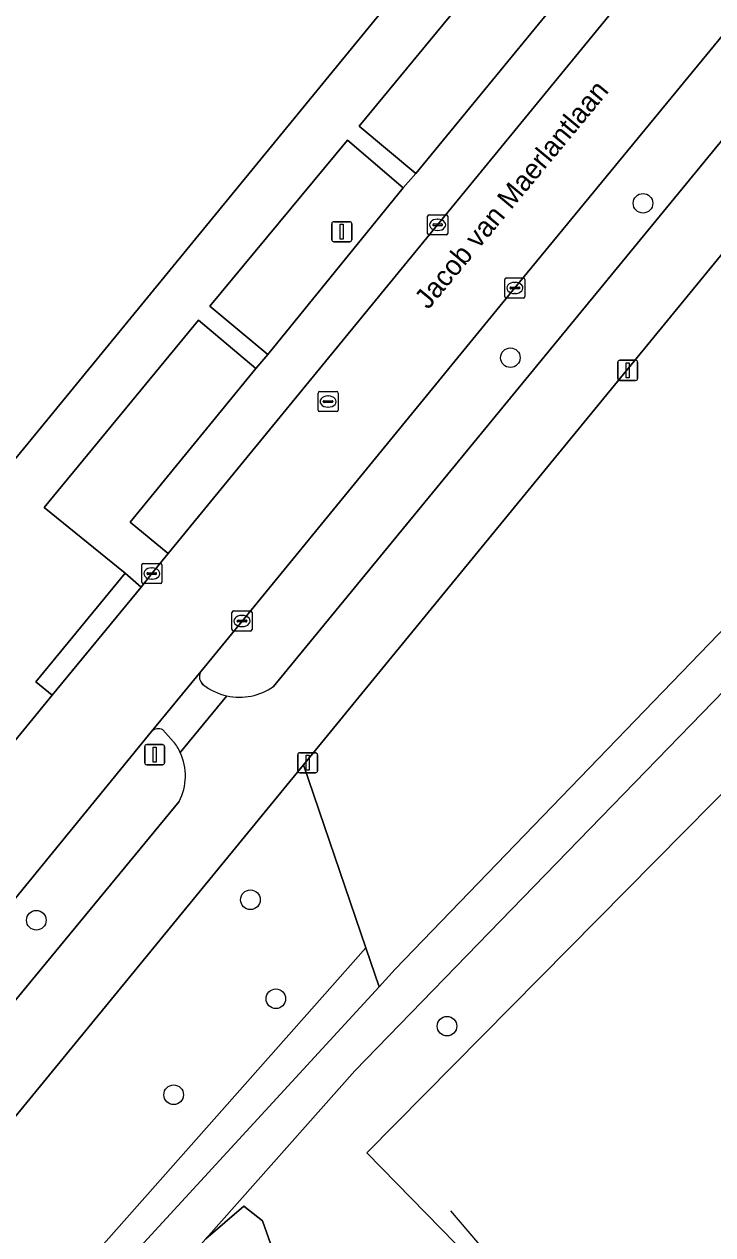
# Model space of a CAD drawing. Extents: x 160349 to 161355, y 381727 to 382854.
# Drawn here: x 160934.1 to 160968.5, y 381971.4 to 382031.7 of the extents above; entities that cross this region are included whole.
import ezdxf

# ---------------------------------------------------------------- set-up
doc = ezdxf.new("R2010")
doc.units = 0
for name, color, linetype in [('IMGEO_Berm_groen', 7, 'Continuous'), ('IMGEO_Boom', 7, 'Continuous'), ('IMGEO_Fietspad_gesloten', 7, 'Continuous'), ('IMGEO_Fietspad_open', 7, 'Continuous'), ('IMGEO_Groenvoorziening', 7, 'Continuous'), ('IMGEO_Hek', 7, 'Continuous'), ('IMGEO_Kolk', 7, 'Continuous'), ('IMGEO_Lichtmast', 7, 'Continuous'), ('IMGEO_Openbare_ruimte_label', 7, 'Continuous'), ('IMGEO_Parkeervlak_open', 7, 'Continuous'), ('IMGEO_Rijbaan_lokaal_open', 7, 'Continuous'), ('IMGEO_Rioolput', 7, 'Continuous'), ('IMGEO_Voetpad_gesloten', 7, 'Continuous'), ('IMGEO_Voetpad_open', 7, 'Continuous')]:
    doc.layers.add(name, color=color, linetype=linetype)

msp = doc.modelspace()

# ---------------------------------------------------------------- linework, layer by layer
at = {"layer": 'IMGEO_Berm_groen'}
for points in [[(160977.843, 382041.946), (160973.022, 382036.094), (160970.983, 382033.618), (160958.625, 382018.578), (160945.001, 382001.967), (160942.965, 381999.472)], [(160946.577, 381998.701), (160947.644, 382000), (160978.867, 382038.025)], [(160942.999, 381998.87), (160943.066, 381998.791)], [(160940.487, 381996.462), (160931.458, 381985.432), (160917.822, 381968.839), (160910.403, 381959.801)], [(160941.587, 381995.948), (160941.049, 381996.534)], [(160914.252, 381959.514), (160941.867, 381992.967)]]:
    msp.add_lwpolyline(points, dxfattribs=at)
for centre, radius, start, end in [((160943.351, 381999.192), 0.477, 144.00703, 222.45805), ((160944.889, 382001.119), 2.957, 231.94134, 257.44147), ((160944.88, 382001.112), 2.948, 257.57231, 305.13262), ((160940.815, 381996.128), 0.468, 60.06083, 134.5404), ((160939.335, 381994.194), 2.854, 25.27298, 37.90616), ((160939.409, 381994.24), 2.768, 332.62628, 25.07844)]:
    msp.add_arc(centre, radius, start, end, dxfattribs=at)
at = {"layer": 'IMGEO_Boom'}
for centre in [(160965.021, 382022.803), (160958.4, 382015.1), (160945.421, 381988.065), (160934.732, 381987.042), (160946.691, 381983.127), (160955.234, 381981.759), (160941.589, 381978.338)]:
    msp.add_circle(centre, 0.489, dxfattribs=at)
at = {"layer": 'IMGEO_Fietspad_gesloten'}
for points in [[(160920.972, 381961.771), (160930.015, 381972.797), (160948.063, 381994.801), (160952.327, 382000), (160980.31, 382034.118), (160983.19, 382037.204), (160985.736, 382040.033), (160986.476, 382040.855), (160994.96, 382049.954), (161000, 382055.359), (161018.426, 382075.121), (161020.27, 382077.268), (161020.313, 382077.319), (161024.035, 382081.674), (161027.907, 382086.255)], [(161008.328, 382069.561), (161008.144, 382069.364), (161000, 382060.672), (160992.234, 382052.382), (160984.775, 382044.42), (160984.715, 382044.355), (160984.593, 382044.223), (160978.867, 382038.025), (160947.644, 382000), (160946.577, 381998.701)], [(160944.246, 381998.233), (160941.916, 381995.413)], [(160941.867, 381992.967), (160914.252, 381959.514)]]:
    msp.add_lwpolyline(points, dxfattribs=at)
for centre, radius, start, end in [((160944.88, 382001.112), 2.948, 257.57231, 305.13262), ((160939.409, 381994.24), 2.768, 332.62628, 25.07844)]:
    msp.add_arc(centre, radius, start, end, dxfattribs=at)
at = {"layer": 'IMGEO_Fietspad_open'}
for points in [[(160942.965, 381999.472), (160940.487, 381996.462)], [(160943.066, 381998.791), (160942.999, 381998.87)], [(160941.916, 381995.413), (160944.246, 381998.233)], [(160941.049, 381996.534), (160941.587, 381995.948)]]:
    msp.add_lwpolyline(points, dxfattribs=at)
for centre, radius, start, end in [((160943.351, 381999.192), 0.477, 144.00703, 222.45805), ((160944.889, 382001.119), 2.957, 231.94134, 257.44147), ((160940.815, 381996.128), 0.468, 60.06083, 134.5404), ((160939.335, 381994.194), 2.854, 25.27298, 37.90616)]:
    msp.add_arc(centre, radius, start, end, dxfattribs=at)
at = {"layer": 'IMGEO_Groenvoorziening'}
for points in [[(160924.933, 382013.986), (160932.226, 382008.305), (160932.496, 382008.634), (160958.918, 382040.842)], [(160983.19, 382037.204), (160980.31, 382034.118), (160952.327, 382000), (160948.063, 381994.801), (160951.191, 381985.661), (160951.842, 381983.726), (160952.645, 381984.6), (160971.09, 382003.681), (160987.697, 382019.509)], [(160995.662, 382024.232), (160976.91, 382006.573), (160950.642, 381979.531), (160943.189, 381971.147), (160945.096, 381972.781), (160946.03, 381972.056), (160948.417, 381965.264), (160952.303, 381955.561), (160957.216, 381943.291), (160957.707, 381940.783), (160965.908, 381946.927), (160989.311, 381962.789)], [(160951.842, 381983.726), (160951.191, 381985.661), (160932.182, 381964.238), (160927.224, 381957.496), (160920.972, 381961.771), (160890.52, 381924.643)], [(160890.677, 381907.844), (160891.108, 381907.876), (160894.311, 381908.969), (160895.463, 381909.644), (160898.554, 381913.782), (160906.494, 381926.014), (160914.767, 381938.069), (160926.176, 381953.998), (160935.546, 381965.997), (160951.842, 381983.726)], [(160948.417, 381965.264), (160946.03, 381972.056), (160945.096, 381972.781), (160943.189, 381971.147)]]:
    msp.add_lwpolyline(points, dxfattribs=at)
for points in [[(160960.19, 382032.206), (160957.382, 382034.583), (160950.845, 382026.65), (160953.681, 382024.287)], [(160953.052, 382023.567), (160950.264, 382025.949), (160943.394, 382017.663), (160946.289, 382015.257)], [(160945.685, 382014.567), (160942.823, 382016.971), (160935.129, 382007.623), (160939.169, 382004.356), (160939.968, 382003.663), (160940.499, 382004.335), (160941.313, 382005.329), (160939.424, 382006.895)], [(160988.316, 381984.387), (160974.279, 381998.738), (160951.234, 381975.44), (160965.27, 381961.089)], [(160965.27, 381961.089), (160951.234, 381975.44), (160974.279, 381998.738), (160988.316, 381984.387)], [(160951.191, 381985.661), (160948.063, 381994.801), (160930.015, 381972.797), (160920.972, 381961.771), (160927.224, 381957.496), (160932.182, 381964.238)]]:
    msp.add_lwpolyline(points, close=True, dxfattribs=at)
at = {"layer": 'IMGEO_Hek'}
for points in [[(160943.189, 381971.147), (160945.096, 381972.781), (160946.03, 381972.056)], [(160955.411, 381972.552), (160961.967, 381964.86)], [(160946.03, 381972.056), (160948.417, 381965.264), (160952.303, 381955.561)]]:
    msp.add_lwpolyline(points, dxfattribs=at)
at = {"layer": 'IMGEO_Kolk'}
for p, q in [((160954.268, 382021.302), (160954.268, 382022.154)), ((160954.343, 382022.228), (160955.195, 382022.228)), ((160954.57, 382021.771), (160954.968, 382021.771)), ((160954.756, 382022.008), (160954.781, 382022.008)), ((160955.269, 382022.154), (160955.269, 382021.302)), ((160955.195, 382021.228), (160954.343, 382021.228)), ((160954.527, 382021.722), (160954.527, 382021.734)), ((160954.965, 382021.685), (160954.567, 382021.685)), ((160954.779, 382021.448), (160954.754, 382021.448)), ((160955.011, 382021.734), (160955.011, 382021.722)), ((160958.124, 382018.152), (160958.124, 382019.004)), ((160958.199, 382019.078), (160959.051, 382019.078)), ((160958.612, 382018.858), (160958.637, 382018.858)), ((160959.125, 382019.004), (160959.125, 382018.152)), ((160958.383, 382018.572), (160958.383, 382018.584)), ((160958.821, 382018.535), (160958.423, 382018.535)), ((160958.426, 382018.621), (160958.824, 382018.621)), ((160958.635, 382018.298), (160958.61, 382018.298)), ((160958.867, 382018.584), (160958.867, 382018.572)), ((160959.051, 382018.078), (160958.199, 382018.078)), ((160940.073, 382004.835), (160940.925, 382004.835)), ((160939.998, 382003.909), (160939.998, 382004.761)), ((160940.257, 382004.329), (160940.257, 382004.341)), ((160940.695, 382004.292), (160940.297, 382004.292)), ((160940.3, 382004.378), (160940.698, 382004.378)), ((160940.486, 382004.615), (160940.511, 382004.615)), ((160940.741, 382004.341), (160940.741, 382004.329)), ((160940.999, 382004.761), (160940.999, 382003.909)), ((160940.925, 382003.835), (160940.073, 382003.835)), ((160940.509, 382004.055), (160940.484, 382004.055)), ((160944.575, 382002.467), (160945.427, 382002.467)), ((160944.5, 382001.541), (160944.5, 382002.393)), ((160944.759, 382001.961), (160944.759, 382001.973)), ((160945.197, 382001.924), (160944.799, 382001.924)), ((160944.802, 382002.01), (160945.2, 382002.01)), ((160944.988, 382002.247), (160945.013, 382002.247)), ((160945.243, 382001.973), (160945.243, 382001.961)), ((160945.501, 382002.393), (160945.501, 382001.541)), ((160945.427, 382001.467), (160944.575, 382001.467)), ((160945.011, 382001.687), (160944.986, 382001.687))]:
    msp.add_line(p, q, dxfattribs=at)
for points in [[(160954.268, 382021.302), (160954.268, 382022.154)], [(160954.343, 382022.228), (160955.195, 382022.228)], [(160955.269, 382022.154), (160955.269, 382021.302)], [(160955.195, 382021.228), (160954.343, 382021.228)], [(160958.124, 382018.152), (160958.124, 382019.004)], [(160958.199, 382019.078), (160959.051, 382019.078)], [(160959.125, 382019.004), (160959.125, 382018.152)], [(160959.051, 382018.078), (160958.199, 382018.078)], [(160940.073, 382004.835), (160940.925, 382004.835)], [(160939.998, 382003.909), (160939.998, 382004.761)], [(160940.999, 382004.761), (160940.999, 382003.909)], [(160940.925, 382003.835), (160940.073, 382003.835)], [(160944.575, 382002.467), (160945.427, 382002.467)], [(160944.5, 382001.541), (160944.5, 382002.393)], [(160945.501, 382002.393), (160945.501, 382001.541)], [(160945.427, 382001.467), (160944.575, 382001.467)]]:
    msp.add_lwpolyline(points, dxfattribs=at)
for centre, radius, start, end in [((160954.345, 382022.152), 0.0765, 91.55205, 178.44795), ((160954.345, 382022.152), 0.0765, 91.55205, 178.44795), ((160954.567, 382021.731), 0.0403, 85.87752, 175.75265), ((160954.972, 382021.733), 0.0386, 1.73085, 96.63898), ((160955.193, 382022.152), 0.0765, 1.55205, 88.44795), ((160955.193, 382022.152), 0.0765, 1.55205, 88.44795), ((160954.345, 382021.304), 0.0765, 181.55205, 268.44795), ((160954.345, 382021.304), 0.0765, 181.55205, 268.44795), ((160954.564, 382021.721), 0.0366, 178.93798, 274.71019), ((160954.968, 382021.728), 0.043, 264.86636, 352.45326), ((160955.193, 382021.304), 0.0765, 271.55205, 358.44795), ((160955.193, 382021.304), 0.0765, 271.55205, 358.44795), ((160958.201, 382019.002), 0.0765, 91.55205, 178.44795), ((160958.201, 382019.002), 0.0765, 91.55205, 178.44795), ((160959.049, 382019.002), 0.0765, 1.55205, 88.44795), ((160959.049, 382019.002), 0.0765, 1.55205, 88.44795), ((160958.201, 382018.154), 0.0765, 181.55205, 268.44795), ((160958.201, 382018.154), 0.0765, 181.55205, 268.44795), ((160958.423, 382018.581), 0.0403, 85.87752, 175.75265), ((160958.42, 382018.571), 0.0366, 178.93798, 274.71019), ((160958.824, 382018.578), 0.043, 264.86636, 352.45326), ((160958.828, 382018.583), 0.0386, 1.73085, 96.63898), ((160959.049, 382018.154), 0.0765, 271.55205, 358.44795), ((160959.049, 382018.154), 0.0765, 271.55205, 358.44795), ((160940.075, 382004.759), 0.0765, 91.55205, 178.44795), ((160940.075, 382004.759), 0.0765, 91.55205, 178.44795), ((160940.923, 382004.759), 0.0765, 1.55205, 88.44795), ((160940.923, 382004.759), 0.0765, 1.55205, 88.44795), ((160940.297, 382004.338), 0.0403, 85.87752, 175.75265), ((160940.294, 382004.328), 0.0366, 178.93798, 274.71019), ((160940.698, 382004.335), 0.043, 264.86636, 352.45326), ((160940.702, 382004.34), 0.0386, 1.73085, 96.63898), ((160940.075, 382003.911), 0.0765, 181.55205, 268.44795), ((160940.075, 382003.911), 0.0765, 181.55205, 268.44795), ((160940.923, 382003.911), 0.0765, 271.55205, 358.44795), ((160940.923, 382003.911), 0.0765, 271.55205, 358.44795), ((160944.577, 382002.391), 0.0765, 91.55205, 178.44795), ((160944.577, 382002.391), 0.0765, 91.55205, 178.44795), ((160945.425, 382002.391), 0.0765, 1.55205, 88.44795), ((160945.425, 382002.391), 0.0765, 1.55205, 88.44795), ((160944.799, 382001.97), 0.0403, 85.87752, 175.75265), ((160944.796, 382001.96), 0.0366, 178.93798, 274.71019), ((160945.2, 382001.967), 0.043, 264.86636, 352.45326), ((160945.204, 382001.972), 0.0386, 1.73085, 96.63898), ((160944.577, 382001.543), 0.0765, 181.55205, 268.44795), ((160944.577, 382001.543), 0.0765, 181.55205, 268.44795), ((160945.425, 382001.543), 0.0765, 271.55205, 358.44795), ((160945.425, 382001.543), 0.0765, 271.55205, 358.44795)]:
    msp.add_arc(centre, radius, start, end, dxfattribs=at)
for centre, major_axis, ratio, start_param, end_param in [((160954.755, 382021.728), (-0.387, 0.002), 0.722429, 4.712389, 7.853982), ((160954.78, 382021.728), (-0.39, 0.002), 0.717154, 1.570796, 4.712389), ((160958.611, 382018.578), (-0.387, 0.002), 0.722429, 4.712389, 7.853982), ((160958.636, 382018.578), (-0.39, 0.002), 0.717154, 1.570796, 4.712389), ((160940.485, 382004.335), (-0.387, 0.002), 0.722429, 4.712389, 7.853982), ((160940.51, 382004.335), (-0.39, 0.002), 0.717154, 1.570796, 4.712389), ((160944.987, 382001.967), (-0.387, 0.002), 0.722429, 4.712389, 7.853982), ((160945.012, 382001.967), (-0.39, 0.002), 0.717154, 1.570796, 4.712389)]:
    msp.add_ellipse(centre, major_axis=major_axis, ratio=ratio, start_param=start_param, end_param=end_param, dxfattribs=at)
at = {"layer": 'IMGEO_Lichtmast'}
for p, q in [((160949.486, 382020.985), (160949.486, 382021.785)), ((160949.486, 382021.785), (160949.486, 382020.985)), ((160949.586, 382021.885), (160950.376, 382021.885)), ((160950.376, 382021.885), (160949.586, 382021.885)), ((160950.476, 382021.785), (160950.476, 382020.985)), ((160950.476, 382020.985), (160950.476, 382021.785)), ((160950.376, 382020.885), (160949.586, 382020.885)), ((160949.586, 382020.885), (160950.376, 382020.885)), ((160963.762, 382014.07), (160963.762, 382014.87)), ((160963.762, 382014.87), (160963.762, 382014.07)), ((160963.862, 382014.97), (160964.652, 382014.97)), ((160964.652, 382014.97), (160963.862, 382014.97)), ((160964.752, 382014.87), (160964.752, 382014.07)), ((160964.752, 382014.07), (160964.752, 382014.87)), ((160964.652, 382013.97), (160963.862, 382013.97)), ((160963.862, 382013.97), (160964.652, 382013.97)), ((160940.243, 381995.8), (160941.033, 381995.8)), ((160941.033, 381995.8), (160940.243, 381995.8)), ((160940.143, 381994.9), (160940.143, 381995.7)), ((160940.143, 381995.7), (160940.143, 381994.9)), ((160941.133, 381995.7), (160941.133, 381994.9)), ((160941.133, 381994.9), (160941.133, 381995.7)), ((160947.781, 381994.496), (160947.781, 381995.296)), ((160947.781, 381995.296), (160947.781, 381994.496)), ((160947.881, 381995.396), (160948.671, 381995.396)), ((160948.671, 381995.396), (160947.881, 381995.396)), ((160948.771, 381995.296), (160948.771, 381994.496)), ((160948.771, 381994.496), (160948.771, 381995.296)), ((160941.033, 381994.8), (160940.243, 381994.8)), ((160940.243, 381994.8), (160941.033, 381994.8)), ((160948.671, 381994.396), (160947.881, 381994.396)), ((160947.881, 381994.396), (160948.671, 381994.396))]:
    msp.add_line(p, q, dxfattribs=at)
for points in [[(160949.906, 382021.76), (160950.056, 382021.76), (160950.056, 382021.01), (160949.906, 382021.01), (160949.906, 382021.76)], [(160964.182, 382014.845), (160964.332, 382014.845), (160964.332, 382014.095), (160964.182, 382014.095), (160964.182, 382014.845)], [(160940.563, 381995.675), (160940.713, 381995.675), (160940.713, 381994.925), (160940.563, 381994.925), (160940.563, 381995.675)], [(160948.201, 381995.271), (160948.351, 381995.271), (160948.351, 381994.521), (160948.201, 381994.521), (160948.201, 381995.271)]]:
    msp.add_lwpolyline(points, dxfattribs=at)
for centre, start, end in [((160949.586, 382021.785), 90, 180), ((160949.586, 382021.785), 90, 180), ((160950.376, 382021.785), 0, 90), ((160950.376, 382021.785), 360, 90), ((160949.586, 382020.985), 180, 270), ((160949.586, 382020.985), 180, 270), ((160950.376, 382020.985), 270, 0), ((160950.376, 382020.985), 270, 0), ((160963.862, 382014.87), 90, 180), ((160963.862, 382014.87), 90, 180), ((160964.652, 382014.87), 0, 90), ((160964.652, 382014.87), 360, 90), ((160963.862, 382014.07), 180, 270), ((160963.862, 382014.07), 180, 270), ((160964.652, 382014.07), 270, 0), ((160964.652, 382014.07), 270, 0), ((160940.243, 381995.7), 90, 180), ((160940.243, 381995.7), 90, 180), ((160941.033, 381995.7), 0, 90), ((160941.033, 381995.7), 360, 90), ((160947.881, 381995.296), 90, 180), ((160947.881, 381995.296), 90, 180), ((160948.671, 381995.296), 0, 90), ((160948.671, 381995.296), 360, 90), ((160940.243, 381994.9), 180, 270), ((160940.243, 381994.9), 180, 270), ((160941.033, 381994.9), 270, 0), ((160941.033, 381994.9), 270, 0), ((160947.881, 381994.496), 180, 270), ((160947.881, 381994.496), 180, 270), ((160948.671, 381994.496), 270, 0), ((160948.671, 381994.496), 270, 0)]:
    msp.add_arc(centre, 0.1, start, end, dxfattribs=at)
at = {"layer": 'IMGEO_Parkeervlak_open'}
msp.add_lwpolyline([(160967.741, 382037.526), (160965.884, 382039.219), (160960.772, 382032.957), (160960.19, 382032.206), (160953.681, 382024.287), (160953.052, 382023.567), (160946.289, 382015.257), (160945.685, 382014.567), (160939.424, 382006.895), (160941.313, 382005.329), (160954.769, 382021.728), (160966.5, 382036.038)], close=True, dxfattribs=at)
at = {"layer": 'IMGEO_Rijbaan_lokaal_open'}
msp.add_lwpolyline([(160917.822, 381968.839), (160931.458, 381985.432), (160940.487, 381996.462), (160942.965, 381999.472), (160945.001, 382001.967), (160958.625, 382018.578), (160970.983, 382033.618), (160973.022, 382036.094), (160969.174, 382039.229), (160967.741, 382037.526), (160966.5, 382036.038), (160954.769, 382021.728), (160941.313, 382005.329), (160940.499, 382004.335), (160939.968, 382003.663), (160935.525, 381998.27), (160932.998, 381995.179), (160930.978, 381992.756), (160927.413, 381988.423), (160913.867, 381971.895), (160908.175, 381964.929)], dxfattribs=at)
at = {"layer": 'IMGEO_Rioolput'}
for p, q in [((160948.798, 382012.487), (160948.798, 382013.339)), ((160948.873, 382013.413), (160949.725, 382013.413)), ((160949.799, 382013.339), (160949.799, 382012.487)), ((160949.057, 382012.907), (160949.057, 382012.919)), ((160949.495, 382012.87), (160949.097, 382012.87)), ((160949.1, 382012.956), (160949.498, 382012.956)), ((160949.286, 382013.193), (160949.311, 382013.193)), ((160949.541, 382012.919), (160949.541, 382012.907)), ((160949.725, 382012.413), (160948.873, 382012.413)), ((160949.309, 382012.633), (160949.284, 382012.633))]:
    msp.add_line(p, q, dxfattribs=at)
for points in [[(160948.798, 382012.487), (160948.798, 382013.339)], [(160948.873, 382013.413), (160949.725, 382013.413)], [(160949.799, 382013.339), (160949.799, 382012.487)], [(160949.725, 382012.413), (160948.873, 382012.413)]]:
    msp.add_lwpolyline(points, dxfattribs=at)
for centre, radius, start, end in [((160948.875, 382013.337), 0.0765, 91.55205, 178.44795), ((160948.875, 382013.337), 0.0765, 91.55205, 178.44795), ((160949.723, 382013.337), 0.0765, 1.55205, 88.44795), ((160949.723, 382013.337), 0.0765, 1.55205, 88.44795), ((160949.097, 382012.916), 0.0403, 85.87752, 175.75265), ((160949.094, 382012.906), 0.0366, 178.93798, 274.71019), ((160949.498, 382012.913), 0.043, 264.86636, 352.45326), ((160949.502, 382012.918), 0.0386, 1.73085, 96.63898), ((160948.875, 382012.489), 0.0765, 181.55205, 268.44795), ((160948.875, 382012.489), 0.0765, 181.55205, 268.44795), ((160949.723, 382012.489), 0.0765, 271.55205, 358.44795), ((160949.723, 382012.489), 0.0765, 271.55205, 358.44795)]:
    msp.add_arc(centre, radius, start, end, dxfattribs=at)
for centre, major_axis, ratio, start_param, end_param in [((160949.285, 382012.913), (-0.387, 0.002), 0.722429, 4.712389, 7.853982), ((160949.31, 382012.913), (-0.39, 0.002), 0.717154, 1.570796, 4.712389)]:
    msp.add_ellipse(centre, major_axis=major_axis, ratio=ratio, start_param=start_param, end_param=end_param, dxfattribs=at)
at = {"layer": 'IMGEO_Voetpad_gesloten'}
for points in [[(160994.375, 382026.192), (160987.697, 382019.509), (160971.09, 382003.681), (160952.645, 381984.6), (160951.842, 381983.726), (160935.546, 381965.997), (160926.176, 381953.998), (160914.767, 381938.069), (160906.494, 381926.014), (160898.554, 381913.782), (160895.463, 381909.644), (160894.311, 381908.969), (160891.108, 381907.876), (160890.677, 381907.844)], [(160892.632, 381905.937), (160892.788, 381905.75), (160893.119, 381906.328), (160893.306, 381906.492), (160894.834, 381907.311), (160898.815, 381909.801), (160901.024, 381913.637), (160914.213, 381933.244), (160926.84, 381951.227), (160935.94, 381962.961), (160943.189, 381971.147), (160950.642, 381979.531), (160976.91, 382006.573), (160995.662, 382024.232)]]:
    msp.add_lwpolyline(points, dxfattribs=at)
at = {"layer": 'IMGEO_Voetpad_open'}
for points in [[(160968.542, 382047.88), (160967.756, 382048.614), (160966.468, 382049.768), (160961.811, 382044.304), (160961.395, 382043.679), (160958.918, 382040.842), (160932.496, 382008.634), (160932.226, 382008.305), (160929.422, 382004.91), (160921.322, 381995.156), (160921.17, 381994.973), (160899.047, 381967.99), (160898.705, 381967.573), (160896.004, 381964.417), (160888.253, 381954.999), (160865.985, 381927.945)], [(160901.593, 381966.764), (160910.958, 381978.11), (160913.812, 381975.725), (160914.407, 381976.45), (160911.543, 381978.839), (160918.833, 381987.696), (160921.69, 381985.335), (160922.265, 381986.038), (160919.406, 381988.378), (160928.151, 381999.086), (160932.998, 381995.179), (160935.525, 381998.27), (160934.714, 381998.935), (160939.169, 382004.356), (160935.129, 382007.623), (160942.823, 382016.971), (160945.685, 382014.567), (160946.289, 382015.257), (160943.394, 382017.663), (160950.264, 382025.949), (160953.052, 382023.567), (160953.681, 382024.287), (160950.845, 382026.65), (160957.382, 382034.583)]]:
    msp.add_lwpolyline(points, dxfattribs=at)
msp.add_lwpolyline([(160939.968, 382003.663), (160939.169, 382004.356), (160934.714, 381998.935), (160935.525, 381998.27)], close=True, dxfattribs=at)

# ---------------------------------------------------------------- texts
at = {"layer": 'IMGEO_Openbare_ruimte_label'}
msp.add_text('Jacob van Maerlantlaan', height=1, rotation=50.35583, dxfattribs=at).set_placement((160954.301, 382017.465))

doc.saveas('drawing.dxf')
